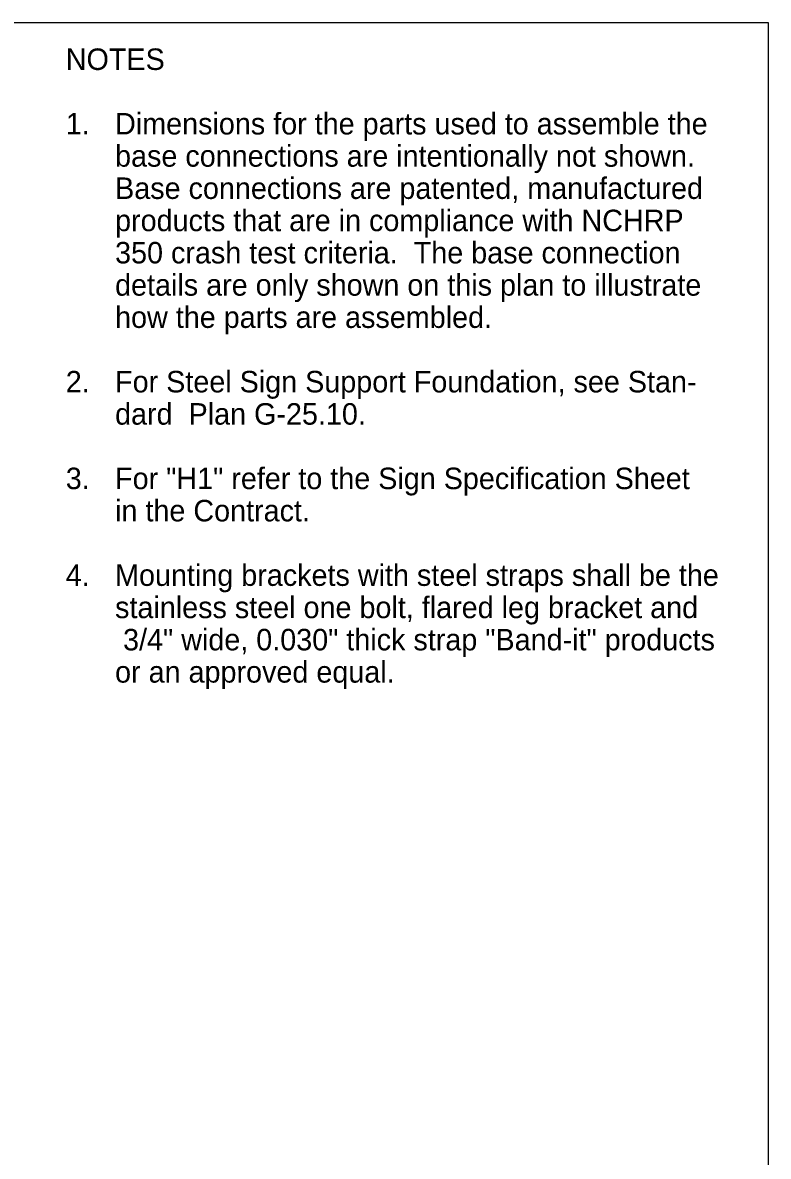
# Model space of a CAD drawing. Extents: x 99862 to 103151, y 103000 to 105076.
# Drawn here: x 102457 to 103151, y 104021 to 105076 of the extents above; entities that cross this region are included whole.
import ezdxf

# ---------------------------------------------------------------- set-up
doc = ezdxf.new("R2010")
doc.units = 0
for name, color, linetype in [('Level 1', 7, 'Continuous'), ('Level 20', 7, 'Continuous'), ('Level 60', 7, 'Continuous')]:
    doc.layers.add(name, color=color, linetype=linetype)

msp = doc.modelspace()

# ---------------------------------------------------------------- linework, layer by layer
at = {"layer": 'Level 1'}
msp.add_lwpolyline([(99862, 102999.5), (103151, 102999.5), (103151, 105075.5), (99862, 105075.5)], close=True, dxfattribs=at)
at = {"layer": 'Level 60'}
msp.add_line((103151, 105075.5), (103151, 105075.5), dxfattribs=at)

# ---------------------------------------------------------------- texts
at = {"layer": 'Level 20'}
for s, p in [('NOTES', (102497.1, 105031.5)), ('1.', (102497.1, 104971.5)), ('Dimensions for the parts used to assemble the ', (102543, 104971.5)), ('base connections are intentionally not shown.  ', (102543, 104941.5)), ('Base connections are patented, manufactured ', (102543, 104911.5)), ('products that are in compliance with NCHRP ', (102543, 104881.5)), ('350 crash test criteria.  The base connection ', (102543, 104851.5)), ('details are only shown on this plan to illustrate ', (102543, 104821.5)), ('how the parts are assembled. ', (102543, 104791.5)), ('2.', (102497.1, 104731.5)), ('For Steel Sign Support Foundation, see Stan-', (102543, 104731.5)), ('dard  Plan G-25.10.', (102543, 104701.5)), ('3.', (102497.1, 104641.5)), ('For "H1" refer to the Sign Specification Sheet  ', (102543, 104641.5)), ('in the Contract.', (102543, 104611.5)), ('4.', (102497.1, 104551.5)), ('Mounting brackets with steel straps shall be the  ', (102543, 104551.5)), ('stainless steel one bolt, flared leg bracket and  ', (102543, 104521.5)), (' 3/4" wide, 0.030" thick strap "Band-it" products  ', (102543, 104491.5)), ('or an approved equal.', (102543, 104461.5))]:
    msp.add_text(s, height=20, dxfattribs=at).set_placement(p)

doc.saveas('drawing.dxf')
